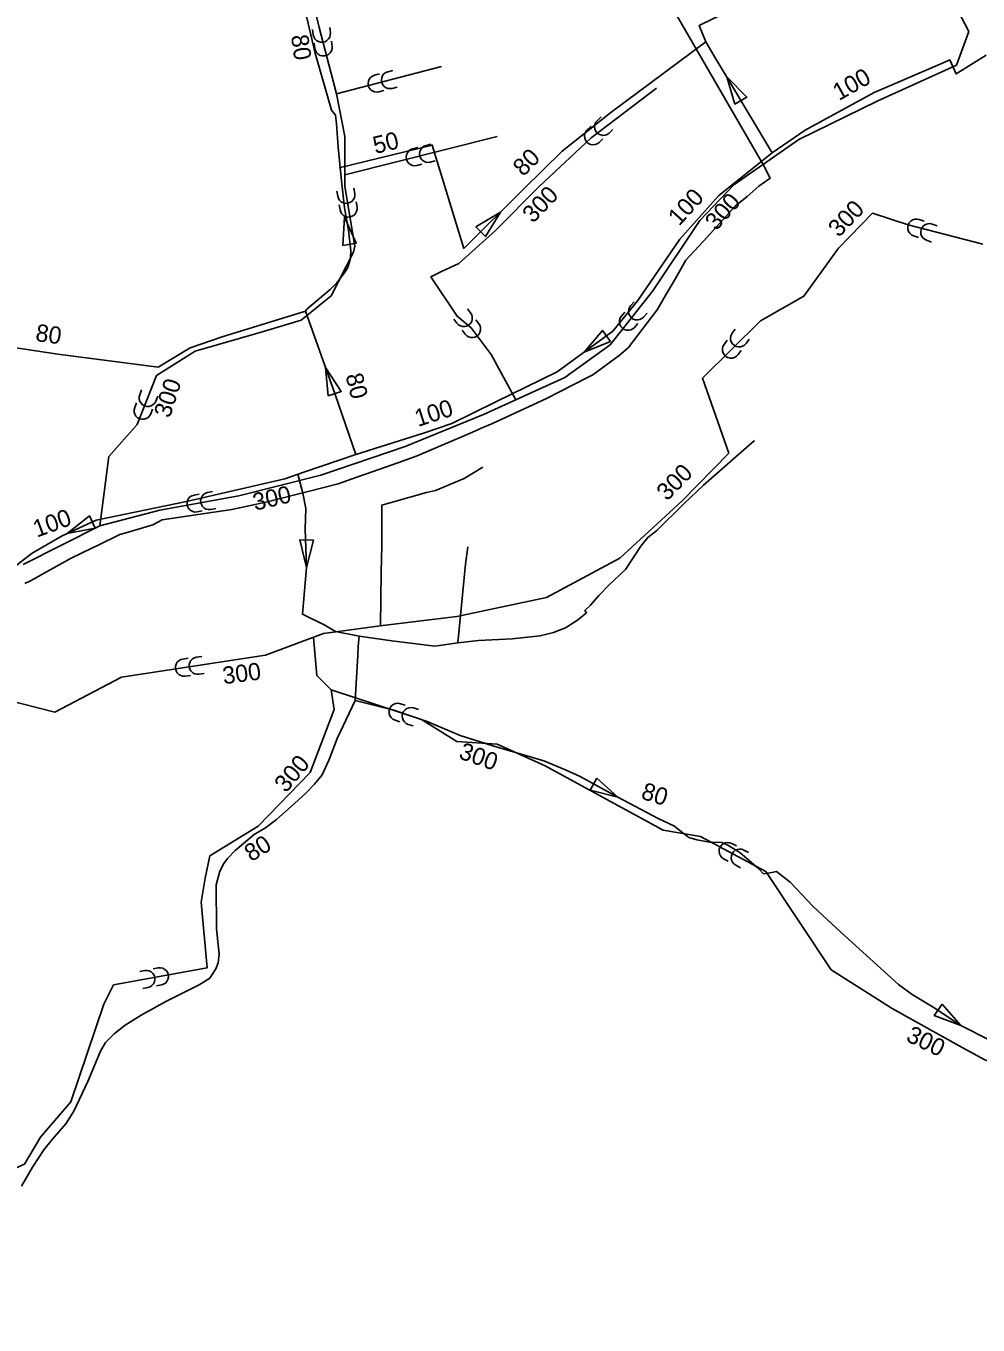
# Model space of a CAD drawing. Extents: x -438814 to -433692, y -1130252 to -1121149.
# Drawn here: x -438249 to -437697, y -1124695 to -1123942 of the extents above; entities that cross this region are included whole.
import ezdxf

# ---------------------------------------------------------------- set-up
doc = ezdxf.new("R2010")
doc.units = 0
for name, color, linetype in [('Vrstva 11', 7, 'Continuous'), ('Vrstva 12', 7, 'Continuous'), ('Vrstva 13', 7, 'Continuous'), ('Vrstva 14', 7, 'Continuous'), ('Vrstva 19', 7, 'Continuous'), ('Vrstva 34', 7, 'Continuous'), ('Vrstva 36', 7, 'Continuous'), ('Vrstva 38', 7, 'Continuous'), ('Vrstva 39', 7, 'Continuous'), ('Vrstva 46', 7, 'Continuous'), ('Vrstva 48', 7, 'Continuous'), ('Vrstva 49', 7, 'Continuous')]:
    doc.layers.add(name, color=color, linetype=linetype)

msp = doc.modelspace()

# ---------------------------------------------------------------- linework, layer by layer
at = {"layer": 'Vrstva 11'}
for points in [[(-437816.67, -1124015.51), (-437843.02, -1123971.22), (-437848.99, -1123961.23), (-437855.1, -1123951.11), (-437858.9, -1123941.65), (-437850.68, -1123937.63), (-437819.41, -1123923.19), (-437816.05, -1123921.08), (-437813.8, -1123919.28), (-437807.29, -1123909.97), (-437802.45, -1123903.55), (-437797.77, -1123899.23), (-437791.38, -1123891.73), (-437788.91, -1123888.02), (-437782.11, -1123880.44), (-437778.7, -1123875.29), (-437761.64, -1123857.22), (-437739.28, -1123842.8), (-437731.18, -1123836.89)], [(-438058, -1124190.31), (-438070.16, -1124155.5), (-438087.24, -1124107.32), (-438086.44, -1124106.1), (-438072.92, -1124094.63), (-438069.1, -1124090.82), (-438064.83, -1124085.11), (-438062.92, -1124082.2), (-438061.29, -1124077.49), (-438061.11, -1124075.95), (-438060.93, -1124072.24), (-438062.31, -1124060.18), (-438064.65, -1124047.22), (-438066.42, -1124031.61), (-438068.25, -1124012.19), (-438069.38, -1123998.53), (-438069.97, -1123993.51), (-438072.3, -1123990.72), (-438081.69, -1123957.74), (-438087.49, -1123933.04)], [(-438273.08, -1124268.41), (-438245.92, -1124247.58), (-438228.49, -1124237.39), (-438208.62, -1124228.37), (-438156.33, -1124217.5), (-438099.2, -1124204.35), (-438088.33, -1124200.5), (-438058, -1124190.31), (-438018.23, -1124177.73), (-438002.39, -1124172.29), (-437977.26, -1124160), (-437941.31, -1124142.43), (-437908.99, -1124118.91), (-437894.51, -1124101.02), (-437870.09, -1124065.56), (-437847.45, -1124040.2), (-437816.67, -1124015.51), (-437797.52, -1124002.24), (-437757.45, -1123980.5), (-437719.2, -1123963.97), (-437713.54, -1123961.48), (-437709.92, -1123969.63), (-437692.49, -1123958.76)], [(-438056.1, -1124295.56), (-438037.27, -1124298.43), (-438012.19, -1124301.4), (-437998.96, -1124299.6), (-437986.92, -1124298.19), (-437967.31, -1124297.11), (-437951.14, -1124295.43), (-437943.49, -1124293.54), (-437936.41, -1124290.84), (-437929.57, -1124286.43), (-437924.3, -1124282.06), (-437925.21, -1124280.83), (-437921.92, -1124277.66), (-437917.23, -1124272.16), (-437911.16, -1124265.93), (-437901.73, -1124257.09), (-437892.77, -1124243.39), (-437888.65, -1124238.47), (-437883.41, -1124234.37), (-437867.76, -1124218.9), (-437856.45, -1124208.15), (-437826.93, -1124182.3)], [(-438091.71, -1124201.7), (-438088.75, -1124212.68), (-438087.02, -1124221.72), (-438087.4, -1124233.4), (-438086.64, -1124255.9), (-438089.12, -1124282.93), (-438076.01, -1124289.32), (-438069.9, -1124292.91), (-438056.1, -1124295.56), (-438056.75, -1124301.69), (-438056.86, -1124306.7), (-438058.44, -1124332.96), (-438068.97, -1124354.89), (-438073.59, -1124367.22), (-438077.68, -1124376.1), (-438082.12, -1124381.42), (-438087.34, -1124386.78), (-438095.62, -1124394.49), (-438104.07, -1124402.01), (-438110.49, -1124406.82), (-438117.13, -1124410.57), (-438119.65, -1124412.76), (-438128.07, -1124419.86), (-438132.52, -1124424.61), (-438134.57, -1124427.5), (-438137.05, -1124431.97), (-438139.08, -1124439.89), (-438138.97, -1124465.29), (-438137.68, -1124476.33), (-438137.4, -1124480.09), (-438137.97, -1124485.02), (-438139.25, -1124488.56), (-438142.82, -1124493.84), (-438148.95, -1124497.84), (-438167.89, -1124507.2), (-438182.58, -1124515.4), (-438191.97, -1124521.24), (-438198.19, -1124526.25), (-438203.22, -1124531.3), (-438206.11, -1124536.33), (-438213.59, -1124553.79), (-438221.72, -1124570.97), (-438226.22, -1124578.39), (-438234.17, -1124587.5), (-438239.05, -1124593.55), (-438245.72, -1124603.41), (-438251.96, -1124614.54)], [(-437998.96, -1124299.6), (-437994.55, -1124253.83), (-437993.19, -1124243.76)], [(-438058.42, -1124332.9), (-438035.97, -1124338.5), (-438016.72, -1124345.03), (-437997.66, -1124353.29), (-437978.66, -1124359.24), (-437949.07, -1124367.86), (-437936.06, -1124373.27), (-437927.89, -1124377.09), (-437906.16, -1124389.08), (-437882.67, -1124401.38), (-437873.26, -1124405.86), (-437871.83, -1124406.88), (-437864.93, -1124412.45), (-437860.33, -1124413.8), (-437852.86, -1124415.04), (-437845.77, -1124415.36), (-437842.27, -1124416.75), (-437835.43, -1124421.09), (-437824.32, -1124430.57), (-437821.68, -1124433.36), (-437816.87, -1124432.68), (-437814.07, -1124432.14), (-437806.1, -1124438.28), (-437792.74, -1124452.46), (-437776.62, -1124467.48), (-437743.21, -1124497.62), (-437735.33, -1124503.48), (-437722.25, -1124511.37), (-437715.16, -1124516.07), (-437707.1, -1124521.34), (-437658.93, -1124545.77)]]:
    msp.add_lwpolyline(points, dxfattribs=at)
at = {"layer": 'Vrstva 12'}
for points in [[(-437838.16, -1123987.22), (-437831.28, -1123983.13), (-437842.9, -1123971.42)], [(-438065.69, -1124069.23), (-438057.82, -1124067.76), (-438064.7, -1124052.76)], [(-437910.39, -1124124.88), (-437915.1, -1124118.41), (-437925.68, -1124131.05)], [(-438074.1, -1124156.38), (-438066.56, -1124153.71), (-438075.67, -1124139.96)], [(-438209.35, -1124233.09), (-438212.66, -1124225.81), (-438225.57, -1124236.06)], [(-438082.62, -1124239.9), (-438090.62, -1124239.89), (-438086.64, -1124255.9)], [(-437918.3, -1124377.92), (-437922.13, -1124384.94), (-437906.16, -1124389.08)], [(-437717.98, -1124508.95), (-437722.53, -1124515.53), (-437707.1, -1124521.34)]]:
    msp.add_lwpolyline(points, close=True, dxfattribs=at)
at = {"layer": 'Vrstva 13'}
for points in [[(-438087.24, -1124107.32), (-438135.67, -1124122.18), (-438154.23, -1124128.52), (-438172.8, -1124139.61), (-438230.97, -1124132.14), (-438288.66, -1124123.51), (-438311.91, -1124072.81), (-438319.59, -1124056.35), (-438327.96, -1124045.25), (-438339.96, -1124041.86), (-438377.03, -1124037.56), (-438409.62, -1124038.24), (-438422.48, -1124035.55), (-438448.29, -1124026.95), (-438457.11, -1124021.74), (-438470.02, -1124006.12), (-438477.01, -1123997.55), (-438486.06, -1123973.09), (-438488.31, -1123960.72), (-438482.88, -1123887.58), (-438483.1, -1123883.34)], [(-438067.71, -1124024.2), (-438013.72, -1124010.95), (-437995.41, -1124070.83), (-437960.69, -1124036.31), (-437938.4, -1124014.48), (-437910.1, -1123992.06), (-437855.1, -1123951.11)]]:
    msp.add_lwpolyline(points, dxfattribs=at)
at = {"layer": 'Vrstva 14'}
msp.add_lwpolyline([(-437988.43, -1124058.25), (-437982.79, -1124063.92), (-437974.26, -1124049.8)], close=True, dxfattribs=at)
at = {"layer": 'Vrstva 34'}
for points in [[(-438206.56, -1124231.61), (-438201.28, -1124191.53), (-438184.84, -1124172.87), (-438173.73, -1124144.59), (-438151.32, -1124130.33), (-438113.07, -1124119.46), (-438089.8, -1124112.47), (-438072.38, -1124098.43), (-438059.48, -1124073.07), (-438058.59, -1124069.54), (-438064.47, -1124034.9), (-438064.47, -1124028.14), (-438064.47, -1124005.92), (-438069.22, -1123981.31), (-438079.39, -1123942.68), (-438084.32, -1123921.69), (-438091.7, -1123888.17), (-438094.43, -1123853.74), (-438089.88, -1123814.16), (-438077.15, -1123781.61)], [(-438250.99, -1124254.05), (-438206.56, -1124231.61), (-438171.83, -1124222.58), (-438126.04, -1124214.21), (-438078.48, -1124202.29), (-438029.53, -1124185.73), (-437984.09, -1124167.17), (-437936.95, -1124145.64), (-437910.59, -1124126.83), (-437885.82, -1124095.5), (-437858.51, -1124054.75), (-437838.91, -1124034.03), (-437801.18, -1124007.78), (-437755.63, -1123985.55), (-437709.64, -1123964.52), (-437702.46, -1123945.06), (-437714.57, -1123921.97)], [(-438308.92, -1124317.08), (-438270.78, -1124330.05), (-438232.63, -1124339.64), (-438193.93, -1124319.41), (-438110.46, -1124306.7), (-438076.83, -1124294.13), (-438044.07, -1124289.63), (-437999.41, -1124284.16), (-437947.43, -1124273.24), (-437905, -1124250.33), (-437868.85, -1124217.12), (-437841.76, -1124189.51), (-437857.04, -1124146.16), (-437823.32, -1124112.77), (-437798.27, -1124098.47), (-437778.05, -1124070.78), (-437758.37, -1124050.48), (-437737.69, -1124057.16), (-437694.33, -1124068.4)], [(-437984.46, -1124197.68), (-437995.2, -1124204.3), (-438011.96, -1124211.16), (-438017.06, -1124212.34), (-438036.32, -1124217.86), (-438043.08, -1124219.74), (-438043.02, -1124242.99), (-438043.32, -1124258.67), (-438043.79, -1124289.52)]]:
    msp.add_lwpolyline(points, dxfattribs=at)
at = {"layer": 'Vrstva 36'}
for p, q in [((-438069.22, -1123981.31), (-438008.43, -1123965.42)), ((-438064.47, -1124028.14), (-437976.04, -1124005.88))]:
    msp.add_line(p, q, dxfattribs=at)
for points in [[(-437883.72, -1123978.01), (-437921.52, -1124006.77), (-437951.85, -1124035.08), (-437976.98, -1124060.44), (-437998.43, -1124079.62), (-438008.39, -1124084.15), (-438014.51, -1124087.26), (-437999.35, -1124110.13), (-437991.2, -1124116.92), (-437979.65, -1124132.32), (-437965.28, -1124158.58)], [(-438082.71, -1124296.33), (-438080.68, -1124318.45), (-438072.31, -1124326.82), (-438020.02, -1124344.04), (-437999.49, -1124356.71), (-437976.17, -1124358.29), (-437948.33, -1124370.75), (-437914.61, -1124389.09), (-437879.85, -1124408.04), (-437858.12, -1124411.89), (-437820.32, -1124432.05), (-437782.35, -1124489.03), (-437747.04, -1124511.45), (-437706.34, -1124534.06), (-437693.21, -1124541.3), (-437638.95, -1124558.7), (-437608.88, -1124582.22), (-437594.16, -1124601.01), (-437514.82, -1124685.5), (-437504.62, -1124699.09)], [(-438072.31, -1124326.82), (-438070.72, -1124338.14), (-438084.53, -1124374.6), (-438114.66, -1124405.79), (-438142.73, -1124423), (-438145.44, -1124435.91), (-438147.89, -1124449.85), (-438144.26, -1124487.89), (-438198.59, -1124497.85), (-438204.18, -1124509.07), (-438223.42, -1124565.68), (-438241.08, -1124586.06), (-438250.36, -1124601.69), (-438274.72, -1124612.47), (-438316.37, -1124626.51), (-438356.89, -1124637.15), (-438399.67, -1124651.19), (-438459.74, -1124674)]]:
    msp.add_lwpolyline(points, dxfattribs=at)
at = {"layer": 'Vrstva 38'}
for p, q in [((-438082.8, -1123946.98), (-438083.17, -1123944)), ((-438072.87, -1123945.75), (-438073.24, -1123942.77)), ((-438081.82, -1123954.92), (-438082.18, -1123951.94)), ((-438071.89, -1123953.69), (-438072.26, -1123950.71)), ((-438058.72, -1124038.92), (-438059.22, -1124035.96)), ((-438068.57, -1124040.6), (-438069.08, -1124037.64)), ((-438057.38, -1124046.81), (-438057.88, -1124043.85)), ((-438067.23, -1124048.48), (-438067.74, -1124045.53)), ((-437731.32, -1124054.08), (-437728.49, -1124055.06)), ((-437723.77, -1124056.7), (-437720.93, -1124057.69)), ((-437734.61, -1124063.52), (-437731.77, -1124064.51)), ((-437727.05, -1124066.15), (-437724.22, -1124067.13)), ((-437898.66, -1124104.02), (-437896.68, -1124101.77)), ((-437903.94, -1124110.04), (-437901.96, -1124107.78)), ((-437891.14, -1124110.62), (-437889.16, -1124108.37)), ((-437896.42, -1124116.63), (-437894.44, -1124114.38)), ((-438183.45, -1124155.69), (-438182.35, -1124152.9)), ((-438174.14, -1124159.34), (-438173.04, -1124156.54)), ((-438186.36, -1124163.14), (-438185.27, -1124160.34)), ((-438177.05, -1124166.79), (-438175.96, -1124163.99)), ((-438151.96, -1124213.81), (-438149.01, -1124213.25)), ((-438144.1, -1124212.33), (-438141.15, -1124211.77)), ((-438150.1, -1124223.64), (-438147.16, -1124223.08)), ((-438142.24, -1124222.15), (-438139.29, -1124221.59))]:
    msp.add_line(p, q, dxfattribs=at)
for centre, start, end in [((-438077.84, -1123946.36), 187.05501, 7.05608), ((-438076.85, -1123954.3), 187.05501, 7.05608), ((-438063.64, -1124039.76), 189.64057, 9.64164), ((-438062.3, -1124047.65), 189.64057, 9.64164), ((-437732.96, -1124058.8), 70.83676, 250.83783), ((-437725.41, -1124061.43), 70.83676, 250.83783), ((-437894.9, -1124107.32), 138.73555, 318.73662), ((-437900.18, -1124113.34), 138.73555, 318.73662), ((-438178.79, -1124157.51), 158.60056, 338.60163), ((-438181.71, -1124164.96), 158.60056, 338.60163), ((-438151.03, -1124218.72), 100.69894, 280.70001), ((-438143.17, -1124217.24), 100.69894, 280.70001)]:
    msp.add_arc(centre, 5, start, end, dxfattribs=at)
at = {"layer": 'Vrstva 39'}
for p, q in [((-438039.54, -1123968.38), (-438036.63, -1123967.62)), ((-438047.28, -1123970.41), (-438044.37, -1123969.65)), ((-438044.75, -1123980.08), (-438041.84, -1123979.32)), ((-438037.01, -1123978.06), (-438034.1, -1123977.3)), ((-437918, -1123996.65), (-437915.8, -1123994.6)), ((-437923.84, -1124002.1), (-437921.65, -1124000.06)), ((-437911.17, -1124003.96), (-437908.98, -1124001.91)), ((-438025.13, -1124013.08), (-438022.22, -1124012.35)), ((-438017.37, -1124011.13), (-438014.46, -1124010.4)), ((-437917.02, -1124009.41), (-437914.83, -1124007.37)), ((-438014.93, -1124020.82), (-438012.02, -1124020.09)), ((-438022.69, -1124022.78), (-438019.78, -1124022.05)), ((-437999.49, -1124114.19), (-438001.29, -1124111.79)), ((-437991.49, -1124108.2), (-437993.29, -1124105.79)), ((-437994.69, -1124120.59), (-437996.49, -1124118.19)), ((-437986.69, -1124114.6), (-437988.49, -1124112.2)), ((-437839.8, -1124120.04), (-437838.04, -1124117.61)), ((-437844.49, -1124126.52), (-437842.73, -1124124.09)), ((-437831.7, -1124125.91), (-437829.94, -1124123.48)), ((-437836.39, -1124132.39), (-437834.63, -1124129.96)), ((-438150.46, -1124307.82), (-438147.49, -1124307.41)), ((-438158.39, -1124308.9), (-438155.42, -1124308.49)), ((-438157.04, -1124318.81), (-438154.06, -1124318.4)), ((-438149.11, -1124317.73), (-438146.14, -1124317.32)), ((-438032.27, -1124334.79), (-438029.42, -1124335.72)), ((-438024.66, -1124337.27), (-438021.81, -1124338.2)), ((-438035.37, -1124344.3), (-438032.51, -1124345.23)), ((-438027.76, -1124346.78), (-438024.91, -1124347.71)), ((-437840.02, -1124415.88), (-437837.37, -1124417.29)), ((-437832.96, -1124419.64), (-437830.32, -1124421.05)), ((-437844.73, -1124424.7), (-437842.08, -1124426.11)), ((-437837.67, -1124428.46), (-437835.02, -1124429.88)), ((-438172.66, -1124488.02), (-438175.61, -1124488.56)), ((-438180.53, -1124489.46), (-438183.48, -1124490)), ((-438178.72, -1124499.29), (-438181.67, -1124499.84)), ((-438170.85, -1124497.85), (-438173.81, -1124498.39))]:
    msp.add_line(p, q, dxfattribs=at)
for centre, start, end in [((-438038.27, -1123973.22), 104.64999, 284.65106), ((-438046.01, -1123975.24), 104.64999, 284.65106), ((-437914.58, -1124000.3), 133.02116, 313.02223), ((-437920.43, -1124005.76), 133.02116, 313.02223), ((-438023.91, -1124017.93), 104.12707, 284.12814), ((-438016.15, -1124015.98), 104.12707, 284.12814), ((-437995.49, -1124111.19), 216.85739, 36.85847), ((-437990.69, -1124117.6), 216.85739, 36.85847), ((-437840.44, -1124129.45), 144.06903, 324.07011), ((-437835.75, -1124122.98), 144.06903, 324.07011), ((-438157.71, -1124313.85), 97.76326, 277.76433), ((-438149.79, -1124312.77), 97.76326, 277.76433), ((-438033.82, -1124339.54), 71.95871, 251.95978), ((-438026.21, -1124342.02), 71.95871, 251.95978), ((-437842.37, -1124420.29), 61.93578, 241.93685), ((-437835.31, -1124424.05), 61.93578, 241.93685), ((-438171.76, -1124492.93), 280.39253, 100.3936), ((-438179.63, -1124494.38), 280.39253, 100.3936)]:
    msp.add_arc(centre, 5, start, end, dxfattribs=at)
at = {"layer": 'Vrstva 46'}
msp.add_lwpolyline([(-437873.18, -1123933.53), (-437821.62, -1124022.59), (-437817.77, -1124030.21), (-437824.28, -1124034.78), (-437831.15, -1124040.68), (-437837.96, -1124046.43), (-437854.3, -1124064.25), (-437866.6, -1124077.67), (-437872.75, -1124088.36), (-437879.53, -1124100.13), (-437883.22, -1124106.54), (-437900.07, -1124128.46), (-437905.32, -1124132.95), (-437920.59, -1124144.17), (-437923.63, -1124145.7), (-437940.04, -1124153.97), (-437947.52, -1124157.82), (-437978.78, -1124172.37), (-437985.72, -1124175.34), (-437987.35, -1124176.04), (-437996.3, -1124179.86), (-438008.89, -1124185.25), (-438022.56, -1124191.1), (-438033.75, -1124195.07), (-438051.94, -1124201.54), (-438054.79, -1124202.55), (-438068.33, -1124207.36), (-438085.79, -1124211.75), (-438110.36, -1124218.03), (-438130.08, -1124222.16), (-438170.4, -1124228.15), (-438175.89, -1124231.16), (-438190.66, -1124235.48), (-438195.02, -1124236.75), (-438207.91, -1124243), (-438211.24, -1124244.61), (-438223.26, -1124250.44), (-438238.86, -1124259.12), (-438244.7, -1124262.37), (-438246.74, -1124263.66), (-438250.08, -1124265.17)], dxfattribs=at)

# ---------------------------------------------------------------- texts
at = {"layer": 'Vrstva 19'}
for s, rotation, p in [('80', 278.32115, (-438095.75, -1123947.56)), ('100', 29.41726, (-437777.84, -1123985.44)), ('50', 13.60783, (-438046.81, -1124016.12)), ('80', 44.96567, (-437960.97, -1124029.56)), ('100', 47.588, (-437870.57, -1124058.28)), ('80', 351.80772, (-438244.32, -1124124.41)), ('80', 284.02465, (-438064.15, -1124144.49)), ('100', 17.93979, (-438022.04, -1124174.38)), ('100', 20.1542, (-438243.13, -1124238.57)), ('80', 342.46214, (-437893.2, -1124389.69)), ('80', 31.85068, (-438118.76, -1124426.72))]:
    msp.add_text(s, height=10, rotation=rotation, dxfattribs=at).set_placement(p)
at = {"layer": 'Vrstva 48'}
for rotation, p in [(46.10648, (-437777.91, -1124064.87)), (72.14363, (-438165.98, -1124169.62)), (45.5533, (-437877.56, -1124217.7)), (13.37194, (-438116.53, -1124222.98)), (7.33277, (-438134.75, -1124323.54))]:
    msp.add_text('300', height=10, rotation=rotation, dxfattribs=at).set_placement(p)
at = {"layer": 'Vrstva 49'}
for rotation, p in [(46.14802, (-437955.31, -1124056.67)), (48.52967, (-437849.01, -1124061.02)), (340.5168, (-437998.95, -1124366.34)), (49.82827, (-438098.62, -1124386.94)), (334.17653, (-437739.56, -1124530.05))]:
    msp.add_text('300', height=10, rotation=rotation, dxfattribs=at).set_placement(p)

doc.saveas('drawing.dxf')
